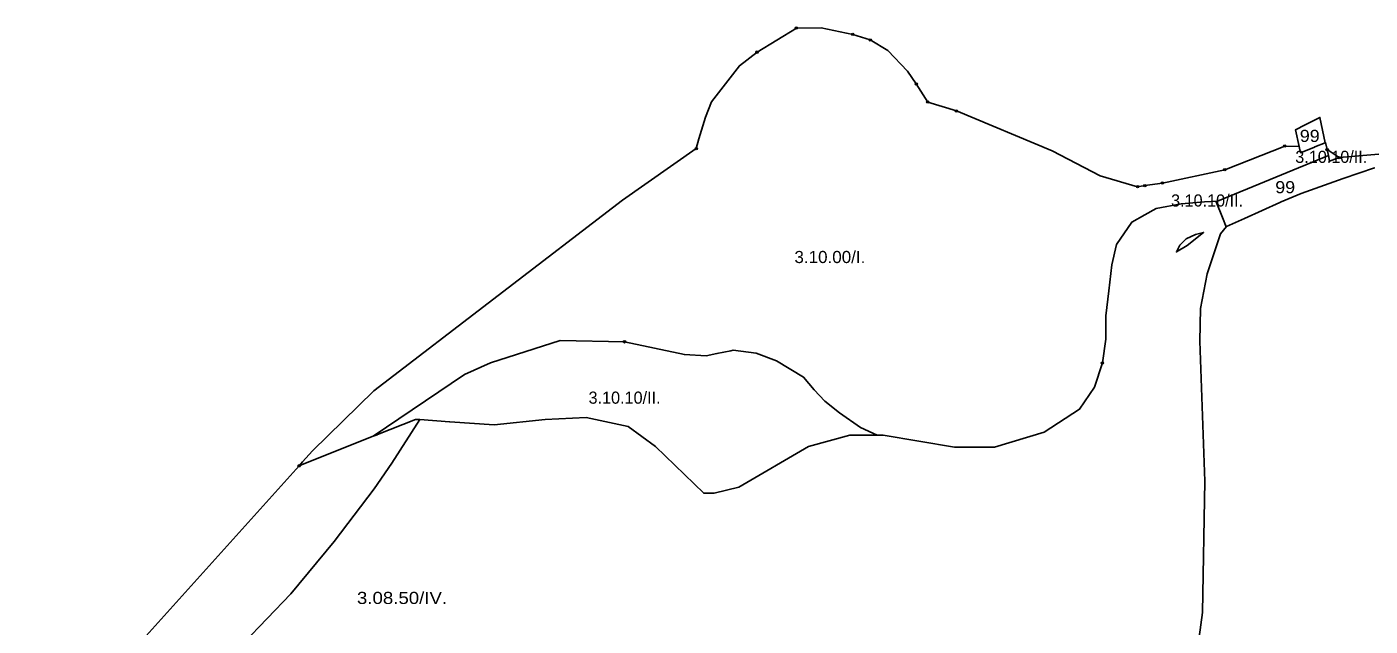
# Model space of a CAD drawing. Extents: x -650455 to -642254, y -1075222 to -1066610.
# Drawn here: x -645923 to -644814, y -1069403 to -1068909 of the extents above; entities that cross this region are included whole.
import ezdxf
from ezdxf.enums import TextEntityAlignment as Align

# ---------------------------------------------------------------- set-up
doc = ezdxf.new("R2010")
doc.units = 0
doc.header["$LTSCALE"] = 4
doc.header["$PDMODE"] = 32
doc.header["$PDSIZE"] = 2
for name, color, linetype, lineweight in [('1', 7, 'Continuous', 25), ('11', 7, 'Continuous', 13), ('12', 7, 'Continuous', 13), ('14', 7, 'Continuous', 13), ('15', 7, 'Continuous', 13)]:
    doc.layers.add(name, color=color, linetype=linetype, lineweight=lineweight)
doc.layers.add('2', color=7, linetype='Continuous')

msp = doc.modelspace()

# ---------------------------------------------------------------- linework, layer by layer
at = {"layer": '1'}
for points in [[(-644794, -1069012.5), (-644839.5, -1069016.5), (-644849.51, -1069009.955), (-644850.813, -1069004.126), (-644851.147, -1069004.26), (-644851.16, -1069004.211), (-644855.56, -1068983.38), (-644867.701, -1068989.497), (-644875.563, -1068993.501), (-644872.563, -1069007.374), (-644884.5, -1069007), (-644934, -1069026.501), (-644985.5, -1069037.501), (-645000, -1069039.622), (-645006, -1069040.5), (-645037, -1069031.5), (-645076.5, -1069011), (-645155.5, -1068978.001), (-645179.25, -1068970.626), (-645188.625, -1068955.75), (-645195.875, -1068945.251), (-645212.063, -1068928.251), (-645226.625, -1068919.376), (-645241.125, -1068914.876), (-645267.188, -1068909.375), (-645287.562, -1068909.625), (-645320.062, -1068929.501), (-645334.5, -1068940.875), (-645357.687, -1068970.375), (-645362.563, -1068983.25), (-645368.25, -1069001.125), (-645370.25, -1069009.125), (-645431, -1069051.5), (-645636.5, -1069209.001), (-645687, -1069258.5), (-645695.188, -1069267.626), (-645695.195, -1069267.614), (-645698.133, -1069270.881), (-645856.5, -1069447.001)], [(-645341.813, -1069175.875), (-645353.25, -1069178.25), (-645362, -1069180.001), (-645380, -1069179), (-645429.5, -1069168.501), (-645482.5, -1069167.501), (-645540, -1069186), (-645561.5, -1069195.501), (-645637, -1069246.5), (-645694.125, -1069269.251), (-645694.109, -1069269.277), (-645698.133, -1069270.881), (-645695.195, -1069267.614), (-645695.188, -1069267.626), (-645687, -1069258.5), (-645636.5, -1069209.001), (-645431, -1069051.5), (-645370.25, -1069009.125), (-645368.25, -1069001.125), (-645362.563, -1068983.25), (-645357.687, -1068970.375), (-645334.5, -1068940.875), (-645320.062, -1068929.501), (-645287.562, -1068909.625), (-645267.188, -1068909.375), (-645241.125, -1068914.876), (-645226.625, -1068919.376), (-645212.063, -1068928.251), (-645195.875, -1068945.251), (-645188.625, -1068955.75), (-645179.25, -1068970.626), (-645155.5, -1068978.001), (-645076.5, -1069011), (-645037, -1069031.5), (-645006, -1069040.5), (-645000, -1069039.622), (-644985.5, -1069037.501), (-644934, -1069026.501), (-644884.5, -1069007), (-644872.563, -1069007.374)], [(-644872.563, -1069007.374), (-644871.437, -1069012.5), (-644859.861, -1069007.77), (-644859.813, -1069007.75), (-644851.147, -1069004.26), (-644850.813, -1069004.126), (-644849.51, -1069009.955), (-644849.5, -1069010.001), (-644848.375, -1069014.875), (-644939.937, -1069052.376), (-644950.812, -1069053), (-644969.937, -1069054.625), (-644990.688, -1069058.625), (-645000, -1069063.822), (-645010.625, -1069069.751), (-645023.375, -1069088.126), (-645027.375, -1069104.876), (-645029.75, -1069126.376), (-645032.188, -1069147.125), (-645032.188, -1069166.25), (-645035.036, -1069185.816), (-645035.062, -1069186), (-645041.5, -1069206), (-645054, -1069224.001), (-645083, -1069243), (-645124, -1069255.5), (-645157, -1069255.5), (-645216, -1069245.501), (-645220.813, -1069245.501), (-645234.625, -1069239.126), (-645252.125, -1069227.25), (-645264.125, -1069217.626), (-645272.875, -1069208.125), (-645281.687, -1069197.75), (-645304, -1069184.125), (-645320.75, -1069177.75), (-645339.858, -1069175.378), (-645339.875, -1069175.375), (-645341.733, -1069175.855), (-645341.813, -1069175.875)], [(-644810.5, -1069025), (-644836.38, -1069033.691), (-644871, -1069046.001), (-644887.558, -1069053.097), (-644888.516, -1069053.508), (-644917.772, -1069066.77), (-644932.672, -1069073.465), (-644932.75, -1069073.5), (-644935.995, -1069065.887), (-644936, -1069065.875), (-644941.25, -1069052.876), (-644939.937, -1069052.376), (-644848.375, -1069014.875), (-644847.625, -1069019.376), (-644847.621, -1069019.397), (-644839.5, -1069016.5), (-644794, -1069012.5)], [(-644958, -1069432.5), (-644952.5, -1069392), (-644950.5, -1069283.5), (-644954.5, -1069168.001), (-644954, -1069141), (-644948.5, -1069112.5), (-644937.5, -1069079.501), (-644932.672, -1069073.465), (-644917.772, -1069066.77), (-644888.516, -1069053.508), (-644887.558, -1069053.097), (-644871, -1069046.001), (-644836.38, -1069033.691), (-644810.5, -1069025)], [(-645461, -1069231), (-645426.5, -1069238.5), (-645404, -1069255), (-645364, -1069293.501), (-645355.5, -1069293.501), (-645335, -1069288.501), (-645277.5, -1069255), (-645243.5, -1069245.501), (-645220.813, -1069245.501), (-645216, -1069245.501), (-645157, -1069255.5), (-645124, -1069255.5), (-645083, -1069243), (-645054, -1069224.001), (-645041.5, -1069206), (-645035.062, -1069186), (-645035.036, -1069185.816), (-645032.188, -1069166.25), (-645032.188, -1069147.125), (-645029.75, -1069126.376), (-645027.375, -1069104.876), (-645023.375, -1069088.126), (-645010.625, -1069069.751), (-645000, -1069063.822), (-644990.688, -1069058.625), (-644969.937, -1069054.625), (-644950.812, -1069053), (-644939.937, -1069052.376), (-644941.25, -1069052.876), (-644936, -1069065.875), (-644935.995, -1069065.887), (-644932.75, -1069073.5), (-644932.672, -1069073.465)], [(-644932.672, -1069073.465), (-644937.5, -1069079.501), (-644948.5, -1069112.5), (-644954, -1069141), (-644954.5, -1069168.001), (-644950.5, -1069283.5), (-644952.5, -1069392), (-644958, -1069432.5)], [(-645960, -1069928), (-645957.5, -1069916.501), (-645945.5, -1069826), (-645941.5, -1069786), (-645925, -1069683.5), (-645928.5, -1069687.5), (-645921.5, -1069660.5), (-645908.5, -1069548.001), (-645886.5, -1069492.001), (-645856.5, -1069447.001), (-645698.133, -1069270.881), (-645694.109, -1069269.277), (-645694.125, -1069269.251), (-645637, -1069246.5), (-645633.75, -1069245.251), (-645633.394, -1069245.058), (-645602, -1069232.501), (-645598.374, -1069232.751)], [(-645763.379, -1069437.622), (-645704.82, -1069376.516), (-645669.175, -1069333.233), (-645636.076, -1069289.95), (-645621.437, -1069268.627), (-645598.374, -1069232.751), (-645573.808, -1069234.452), (-645573.688, -1069234.5), (-645537, -1069237.001), (-645495, -1069232.501), (-645461, -1069231)], [(-645598.374, -1069232.751), (-645621.437, -1069268.627), (-645636.076, -1069289.95), (-645669.175, -1069333.233), (-645704.82, -1069376.516), (-645763.379, -1069437.622)]]:
    msp.add_lwpolyline(points, dxfattribs=at)
for points in [[(-644851.147, -1069004.26), (-644859.813, -1069007.75), (-644859.861, -1069007.77), (-644871.437, -1069012.5), (-644872.563, -1069007.374), (-644875.563, -1068993.501), (-644867.701, -1068989.497), (-644855.56, -1068983.38), (-644851.16, -1069004.211)], [(-644839.5, -1069016.5), (-644847.621, -1069019.397), (-644847.625, -1069019.376), (-644848.375, -1069014.875), (-644849.5, -1069010.001), (-644849.51, -1069009.955)], [(-644965, -1069089), (-644951.514, -1069078.254), (-644958.188, -1069079.876), (-644965.937, -1069083.625), (-644971, -1069088.876), (-644973.937, -1069094.375), (-644973.944, -1069094.389)], [(-644965, -1069089), (-644973.944, -1069094.389), (-644973.937, -1069094.375), (-644971, -1069088.876), (-644965.937, -1069083.625), (-644958.188, -1069079.876), (-644951.514, -1069078.254)], [(-645220.813, -1069245.501), (-645243.5, -1069245.501), (-645277.5, -1069255), (-645335, -1069288.501), (-645355.5, -1069293.501), (-645364, -1069293.501), (-645404, -1069255), (-645426.5, -1069238.5), (-645461, -1069231), (-645495, -1069232.501), (-645537, -1069237.001), (-645573.688, -1069234.5), (-645573.808, -1069234.452), (-645598.374, -1069232.751), (-645602, -1069232.501), (-645633.394, -1069245.058), (-645633.75, -1069245.251), (-645637, -1069246.5), (-645561.5, -1069195.501), (-645540, -1069186), (-645482.5, -1069167.501), (-645429.5, -1069168.501), (-645380, -1069179), (-645362, -1069180.001), (-645353.25, -1069178.25), (-645341.813, -1069175.875), (-645341.733, -1069175.855), (-645339.875, -1069175.375), (-645339.858, -1069175.378), (-645320.75, -1069177.75), (-645304, -1069184.125), (-645281.687, -1069197.75), (-645272.875, -1069208.125), (-645264.125, -1069217.626), (-645252.125, -1069227.25), (-645234.625, -1069239.126)]]:
    msp.add_lwpolyline(points, close=True, dxfattribs=at)
at = {"layer": '11'}
for p, q in [((-645179.25, -1068970.626), (-645188.625, -1068955.75)), ((-645000, -1069039.622), (-644985.5, -1069037.501))]:
    msp.add_line(p, q, dxfattribs=at)
for points in [[(-645370.25, -1069009.125), (-645368.25, -1069001.125), (-645362.563, -1068983.25), (-645357.687, -1068970.375), (-645334.5, -1068940.875), (-645320.062, -1068929.501), (-645287.562, -1068909.625)], [(-645241.125, -1068914.876), (-645267.188, -1068909.375), (-645287.562, -1068909.625), (-645320.062, -1068929.501)], [(-645287.562, -1068909.625), (-645267.188, -1068909.375), (-645241.125, -1068914.876), (-645226.625, -1068919.376)], [(-645188.625, -1068955.75), (-645195.875, -1068945.251), (-645212.063, -1068928.251), (-645226.625, -1068919.376), (-645241.125, -1068914.876)], [(-645226.625, -1068919.376), (-645212.063, -1068928.251), (-645195.875, -1068945.251), (-645188.625, -1068955.75), (-645179.25, -1068970.626), (-645155.5, -1068978.001)], [(-645320.062, -1068929.501), (-645334.5, -1068940.875), (-645357.687, -1068970.375), (-645362.563, -1068983.25), (-645368.25, -1069001.125), (-645370.25, -1069009.125), (-645431, -1069051.5), (-645636.5, -1069209.001), (-645687, -1069258.5), (-645695.188, -1069267.626), (-645695.195, -1069267.614), (-645698.133, -1069270.881), (-645694.109, -1069269.277), (-645694.125, -1069269.251), (-645637, -1069246.5), (-645561.5, -1069195.501), (-645540, -1069186), (-645482.5, -1069167.501), (-645429.5, -1069168.501)], [(-645006, -1069040.5), (-645037, -1069031.5), (-645076.5, -1069011), (-645155.5, -1068978.001), (-645179.25, -1068970.626)], [(-645155.5, -1068978.001), (-645076.5, -1069011), (-645037, -1069031.5), (-645006, -1069040.5), (-645000, -1069039.622)], [(-644884.5, -1069007), (-644872.563, -1069007.374), (-644875.563, -1068993.501), (-644867.701, -1068989.497), (-644855.56, -1068983.38), (-644851.16, -1069004.211), (-644851.147, -1069004.26), (-644850.813, -1069004.126), (-644849.51, -1069009.955), (-644839.5, -1069016.5), (-644794, -1069012.5), (-644730, -1069011.5), (-644677, -1069006.501), (-644667.5, -1068997.501)], [(-644985.5, -1069037.501), (-644934, -1069026.501), (-644884.5, -1069007)], [(-644849.51, -1069009.955), (-644850.813, -1069004.126), (-644851.147, -1069004.26), (-644859.813, -1069007.75), (-644859.861, -1069007.77), (-644871.437, -1069012.5), (-644872.563, -1069007.374), (-644884.5, -1069007), (-644934, -1069026.501)], [(-645941.5, -1069786), (-645925, -1069683.5), (-645928.5, -1069687.5), (-645921.5, -1069660.5), (-645908.5, -1069548.001), (-645886.5, -1069492.001), (-645856.5, -1069447.001), (-645698.133, -1069270.881), (-645695.195, -1069267.614), (-645695.188, -1069267.626), (-645687, -1069258.5), (-645636.5, -1069209.001), (-645431, -1069051.5), (-645370.25, -1069009.125)], [(-645429.5, -1069168.501), (-645380, -1069179), (-645362, -1069180.001), (-645353.25, -1069178.25), (-645341.813, -1069175.875), (-645341.733, -1069175.855), (-645339.875, -1069175.375), (-645339.858, -1069175.378), (-645320.75, -1069177.75), (-645304, -1069184.125), (-645281.687, -1069197.75), (-645272.875, -1069208.125), (-645264.125, -1069217.626), (-645252.125, -1069227.25), (-645234.625, -1069239.126), (-645220.813, -1069245.501), (-645216, -1069245.501), (-645157, -1069255.5), (-645124, -1069255.5), (-645083, -1069243), (-645054, -1069224.001), (-645041.5, -1069206), (-645035.062, -1069186), (-645035.036, -1069185.816), (-645032.188, -1069166.25), (-645032.188, -1069147.125), (-645029.75, -1069126.376), (-645027.375, -1069104.876), (-645023.375, -1069088.126), (-645010.625, -1069069.751), (-645000, -1069063.822), (-644990.688, -1069058.625), (-644969.937, -1069054.625), (-644950.812, -1069053), (-644939.937, -1069052.376), (-644848.375, -1069014.875), (-644849.5, -1069010.001), (-644849.51, -1069009.955)], [(-644810.5, -1069025), (-644836.38, -1069033.691), (-644871, -1069046.001), (-644887.558, -1069053.097), (-644888.516, -1069053.508), (-644917.772, -1069066.77), (-644932.672, -1069073.465), (-644937.5, -1069079.501), (-644948.5, -1069112.5), (-644954, -1069141), (-644954.5, -1069168.001), (-644950.5, -1069283.5), (-644952.5, -1069392), (-644958, -1069432.5), (-644973, -1069470.5), (-645000, -1069517.419), (-645003.5, -1069523.501), (-645037, -1069572.001), (-645098.5, -1069631), (-645124.5, -1069647.5), (-645146, -1069654.001), (-645167.5, -1069654.001)], [(-644934, -1069026.501), (-644985.5, -1069037.501), (-645000, -1069039.622), (-645006, -1069040.5)]]:
    msp.add_lwpolyline(points, dxfattribs=at)
for p in [(-645287.562, -1068909.625), (-645241.125, -1068914.876), (-645226.625, -1068919.376), (-645320.062, -1068929.501), (-645188.625, -1068955.75), (-645179.25, -1068970.626), (-645155.5, -1068978.001), (-645370.25, -1069009.125), (-644884.5, -1069007), (-644849.51, -1069009.955), (-644934, -1069026.501), (-645006, -1069040.5), (-645000, -1069039.622), (-644985.5, -1069037.501)]:
    msp.add_point(p, dxfattribs=at)
at = {"layer": '12'}
for points in [[(-644839.5, -1069016.5), (-644849.51, -1069009.955), (-644849.5, -1069010.001), (-644848.375, -1069014.875), (-644847.625, -1069019.376)], [(-644847.625, -1069019.376), (-644847.621, -1069019.397), (-644839.5, -1069016.5)], [(-645429.5, -1069168.501), (-645482.5, -1069167.501), (-645540, -1069186), (-645561.5, -1069195.501), (-645637, -1069246.5), (-645633.75, -1069245.251), (-645633.394, -1069245.058), (-645602, -1069232.501), (-645598.374, -1069232.751), (-645573.808, -1069234.452), (-645573.688, -1069234.5), (-645537, -1069237.001), (-645495, -1069232.501), (-645461, -1069231), (-645426.5, -1069238.5), (-645404, -1069255), (-645364, -1069293.501)], [(-645364, -1069293.501), (-645355.5, -1069293.501), (-645335, -1069288.501), (-645277.5, -1069255), (-645243.5, -1069245.501), (-645220.813, -1069245.501), (-645234.625, -1069239.126), (-645252.125, -1069227.25), (-645264.125, -1069217.626), (-645272.875, -1069208.125), (-645281.687, -1069197.75), (-645304, -1069184.125), (-645320.75, -1069177.75), (-645339.858, -1069175.378), (-645339.875, -1069175.375), (-645341.733, -1069175.855), (-645341.813, -1069175.875), (-645353.25, -1069178.25), (-645362, -1069180.001), (-645380, -1069179), (-645429.5, -1069168.501)]]:
    msp.add_lwpolyline(points, dxfattribs=at)
for p in [(-644839.5, -1069016.5), (-645429.5, -1069168.501)]:
    msp.add_point(p, dxfattribs=at)
at = {"layer": '14'}
for points in [[(-644958, -1069432.5), (-644952.5, -1069392), (-644950.5, -1069283.5), (-644954.5, -1069168.001), (-644954, -1069141), (-644948.5, -1069112.5), (-644937.5, -1069079.501), (-644932.672, -1069073.465), (-644932.75, -1069073.5), (-644935.995, -1069065.887), (-644936, -1069065.875), (-644941.25, -1069052.876), (-644939.937, -1069052.376), (-644950.812, -1069053), (-644969.937, -1069054.625), (-644990.688, -1069058.625), (-645000, -1069063.822), (-645010.625, -1069069.751), (-645023.375, -1069088.126), (-645027.375, -1069104.876), (-645029.75, -1069126.376), (-645032.188, -1069147.125)], [(-645032.188, -1069147.125), (-645032.188, -1069166.25), (-645035.036, -1069185.816), (-645035.062, -1069186)], [(-645035.062, -1069186), (-645041.5, -1069206), (-645054, -1069224.001), (-645083, -1069243), (-645124, -1069255.5), (-645157, -1069255.5), (-645216, -1069245.501), (-645220.813, -1069245.501), (-645243.5, -1069245.501), (-645277.5, -1069255), (-645335, -1069288.501), (-645355.5, -1069293.501), (-645364, -1069293.501), (-645404, -1069255), (-645426.5, -1069238.5), (-645461, -1069231), (-645495, -1069232.501), (-645537, -1069237.001), (-645573.688, -1069234.5), (-645573.808, -1069234.452), (-645598.374, -1069232.751), (-645621.437, -1069268.627), (-645636.076, -1069289.95), (-645669.175, -1069333.233), (-645704.82, -1069376.516), (-645763.379, -1069437.622)]]:
    msp.add_lwpolyline(points, dxfattribs=at)
msp.add_point((-645035.062, -1069186), dxfattribs=at)
at = {"layer": '15'}
for points in [[(-645854.14, -1069705.005), (-645856.947, -1069657.538), (-645856.947, -1069611.709), (-645854.401, -1069578.61), (-645844.217, -1069553.15), (-645811.118, -1069499.682), (-645798.388, -1069481.86), (-645763.379, -1069437.622), (-645704.82, -1069376.516), (-645669.175, -1069333.233), (-645636.076, -1069289.95), (-645621.437, -1069268.627), (-645598.374, -1069232.751), (-645602, -1069232.501), (-645633.394, -1069245.058), (-645633.75, -1069245.251), (-645637, -1069246.5), (-645694.125, -1069269.251), (-645694.109, -1069269.277), (-645698.133, -1069270.881)], [(-645698.133, -1069270.881), (-645856.5, -1069447.001), (-645886.5, -1069492.001), (-645908.5, -1069548.001), (-645921.5, -1069660.5)]]:
    msp.add_lwpolyline(points, dxfattribs=at)
msp.add_point((-645698.133, -1069270.881), dxfattribs=at)

# ---------------------------------------------------------------- texts
at = {"layer": '2'}
for s, width, p in [('99', 1.1, (-644863.885, -1069003.583)), ('99', 1.1, (-644884.152, -1069045.92)), ('3.10.00/I.', 1.05, (-645259.949, -1069103.522)), ('3.08.50/IV.', 1.15, (-645613.096, -1069384.866))]:
    msp.add_text(s, height=10, dxfattribs=dict(at, width=width)).set_placement(p, align=Align.CENTER)
for p in [(-644846.118, -1069020.872), (-644948.622, -1069056.876), (-645429.422, -1069219.594)]:
    msp.add_text('3.10.10/II.', height=10, dxfattribs=at).set_placement(p, align=Align.CENTER)

doc.saveas('drawing.dxf')
